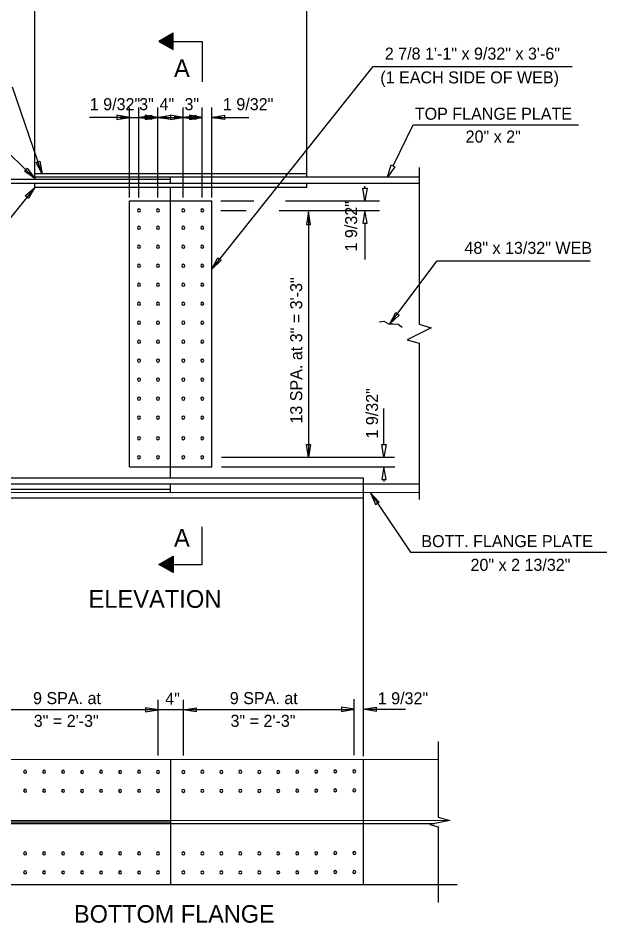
# Model space of a CAD drawing. Extents: x 4944 to 17449, y 3824 to 49087.
# Drawn here: x 13343 to 13907, y 39783 to 40650 of the extents above; entities that cross this region are included whole.
import ezdxf

# ---------------------------------------------------------------- set-up
doc = ezdxf.new("R2010")
doc.units = 0
for name, color, linetype in [('1', 7, 'Continuous'), ('2', 7, 'Continuous'), ('36_S_LINES', 7, 'Continuous'), ('3A', 7, 'Continuous'), ('4', 7, 'Continuous'), ('7', 7, 'Continuous'), ('BEAM', 7, 'Continuous'), ('Level 25', 7, 'Continuous')]:
    doc.layers.add(name, color=color, linetype=linetype)

# ---------------------------------------------------------------- blocks, each defined once
blk = doc.blocks.new('SC1136')
at = {"layer": '1'}
for p, q in [((0.4684, 0.5391), (0.5316, 0.5391)), ((0.4707, 0.543), (0.5293, 0.543)), ((0.4729, 0.5469), (0.5271, 0.5469)), ((0.4752, 0.5508), (0.5248, 0.5508)), ((0.4774, 0.5547), (0.5226, 0.5547)), ((0.4797, 0.5586), (0.5203, 0.5586)), ((0.482, 0.5625), (0.518, 0.5625)), ((0.4842, 0.5664), (0.5158, 0.5664)), ((0.4865, 0.5703), (0.5135, 0.5703)), ((0.4887, 0.5742), (0.5113, 0.5742)), ((0.491, 0.5781), (0.509, 0.5781)), ((0.4932, 0.582), (0.5068, 0.582)), ((0.4955, 0.5859), (0.5045, 0.5859)), ((0.4977, 0.5898), (0.5023, 0.5898)), ((0.4188, 0.4531), (0.5812, 0.4531)), ((0.4211, 0.457), (0.5789, 0.457)), ((0.4233, 0.4609), (0.5767, 0.4609)), ((0.4256, 0.4648), (0.5744, 0.4648)), ((0.4278, 0.4688), (0.5722, 0.4688)), ((0.4301, 0.4727), (0.5699, 0.4727)), ((0.4323, 0.4766), (0.5677, 0.4766)), ((0.4346, 0.4805), (0.5654, 0.4805)), ((0.4369, 0.4844), (0.5631, 0.4844)), ((0.4391, 0.4883), (0.5609, 0.4883)), ((0.4414, 0.4922), (0.5586, 0.4922)), ((0.4436, 0.4961), (0.5564, 0.4961)), ((0.4459, 0.5), (0.5541, 0.5)), ((0.4481, 0.5039), (0.5519, 0.5039)), ((0.4504, 0.5078), (0.5496, 0.5078)), ((0.4526, 0.5117), (0.5474, 0.5117)), ((0.4549, 0.5156), (0.5451, 0.5156)), ((0.4571, 0.5195), (0.5429, 0.5195)), ((0.4594, 0.5234), (0.5406, 0.5234)), ((0.4617, 0.5273), (0.5383, 0.5273)), ((0.4639, 0.5312), (0.5361, 0.5312)), ((0.4662, 0.5352), (0.5338, 0.5352))]:
    blk.add_line(p, q, dxfattribs=at)
blk = doc.blocks.new('DWG070')
at = {"layer": '1'}
blk.add_lwpolyline([(0, 0), (0.1406, -0.0812), (0.1406, 0.0812)], close=True, dxfattribs=at)
at = {"layer": '1', "rotation": 90}
blk.add_blockref('SC1136', (0.5945, -0.5), dxfattribs=at)
blk = doc.blocks.new('ARROWH')
at = {"layer": '1'}
blk.add_lwpolyline([(0.1231, -0.0212), (0.1231, 0.0205), (-0.0019, -0.0003)], close=True, dxfattribs=at)

msp = doc.modelspace()

# ---------------------------------------------------------------- linework, layer by layer
at = {"layer": '1'}
for centre, start, end in [((13458.76, 40465.41), 0, 180), ((13476.95, 40465.41), 0, 180), ((13501.21, 40465.41), 0, 180), ((13519.4, 40465.41), 0, 180), ((13458.76, 40465.41), 180, 0), ((13476.95, 40465.41), 180, 0), ((13501.21, 40465.41), 180, 0), ((13519.4, 40465.41), 180, 0), ((13458.76, 40448.76), 0, 180), ((13458.76, 40448.76), 180, 0), ((13476.95, 40448.76), 0, 180), ((13476.95, 40448.76), 180, 0), ((13501.21, 40448.76), 0, 180), ((13501.21, 40448.76), 180, 0), ((13519.4, 40448.76), 0, 180), ((13519.4, 40448.76), 180, 0), ((13458.76, 40430.56), 0, 180), ((13476.95, 40430.56), 0, 180), ((13501.21, 40430.56), 0, 180), ((13519.4, 40430.56), 0, 180), ((13458.76, 40430.56), 180, 0), ((13476.95, 40430.56), 180, 0), ((13501.21, 40430.56), 180, 0), ((13519.4, 40430.56), 180, 0), ((13458.76, 40412.37), 0, 180), ((13476.95, 40412.37), 0, 180), ((13501.21, 40412.37), 0, 180), ((13519.4, 40412.37), 0, 180), ((13458.76, 40412.37), 180, 0), ((13476.95, 40412.37), 180, 0), ((13501.21, 40412.37), 180, 0), ((13519.4, 40412.37), 180, 0), ((13458.76, 40394.18), 0, 180), ((13458.76, 40394.18), 180, 0), ((13476.95, 40394.18), 0, 180), ((13476.95, 40394.18), 180, 0), ((13501.21, 40394.18), 0, 180), ((13501.21, 40394.18), 180, 0), ((13519.4, 40394.18), 0, 180), ((13519.4, 40394.18), 180, 0), ((13458.76, 40375.98), 0, 180), ((13458.76, 40375.98), 180, 0), ((13476.95, 40375.98), 0, 180), ((13476.95, 40375.98), 180, 0), ((13501.21, 40375.98), 0, 180), ((13501.21, 40375.98), 180, 0), ((13519.4, 40375.98), 0, 180), ((13519.4, 40375.98), 180, 0), ((13458.76, 40357.79), 0, 180), ((13458.76, 40357.79), 180, 0), ((13476.95, 40357.79), 0, 180), ((13476.95, 40357.79), 180, 0), ((13501.21, 40357.79), 0, 180), ((13501.21, 40357.79), 180, 0), ((13519.4, 40357.79), 0, 180), ((13519.4, 40357.79), 180, 0), ((13458.76, 40339.6), 0, 180), ((13458.76, 40339.6), 180, 0), ((13476.95, 40339.6), 0, 180), ((13476.95, 40339.6), 180, 0), ((13501.21, 40339.6), 0, 180), ((13501.21, 40339.6), 180, 0), ((13519.4, 40339.6), 0, 180), ((13519.4, 40339.6), 180, 0), ((13458.76, 40321.41), 0, 180), ((13458.76, 40321.41), 180, 0), ((13476.95, 40321.41), 0, 180), ((13476.95, 40321.41), 180, 0), ((13501.21, 40321.41), 0, 180), ((13501.21, 40321.41), 180, 0), ((13519.4, 40321.41), 0, 180), ((13519.4, 40321.41), 180, 0), ((13458.76, 40303.21), 0, 180), ((13458.76, 40303.21), 180, 0), ((13476.95, 40303.21), 0, 180), ((13476.95, 40303.21), 180, 0), ((13501.21, 40303.21), 0, 180), ((13501.21, 40303.21), 180, 0), ((13519.4, 40303.21), 0, 180), ((13519.4, 40303.21), 180, 0), ((13458.76, 40285.02), 0, 180), ((13458.76, 40285.02), 180, 0), ((13476.95, 40285.02), 0, 180), ((13476.95, 40285.02), 180, 0), ((13501.21, 40285.02), 0, 180), ((13501.21, 40285.02), 180, 0), ((13519.4, 40285.02), 0, 180), ((13519.4, 40285.02), 180, 0), ((13458.76, 40266.83), 0, 180), ((13458.76, 40266.83), 180, 0), ((13476.95, 40266.83), 0, 180), ((13476.95, 40266.83), 180, 0), ((13501.21, 40266.83), 0, 180), ((13501.21, 40266.83), 180, 0), ((13519.4, 40266.83), 0, 180), ((13519.4, 40266.83), 180, 0), ((13458.76, 40247.09), 0, 180), ((13458.76, 40247.09), 180, 0), ((13476.95, 40247.09), 0, 180), ((13476.95, 40247.09), 180, 0), ((13501.21, 40247.09), 0, 180), ((13501.21, 40247.09), 180, 0), ((13519.4, 40247.09), 0, 180), ((13519.4, 40247.09), 180, 0), ((13458.76, 40228.9), 0, 180), ((13458.76, 40228.9), 180, 0), ((13476.95, 40228.9), 0, 180), ((13476.95, 40228.9), 180, 0), ((13501.21, 40228.9), 0, 180), ((13501.21, 40228.9), 180, 0), ((13519.4, 40228.9), 0, 180), ((13519.4, 40228.9), 180, 0), ((13349.66, 39927.54), 0, 180), ((13367.86, 39927.48), 0, 180), ((13386.05, 39927.42), 0, 180), ((13404.24, 39927.37), 0, 180), ((13422.43, 39927.42), 0, 180), ((13440.63, 39927.37), 0, 180), ((13458.82, 39927.42), 0, 180), ((13477.01, 39927.37), 0, 180), ((13501.27, 39927.37), 0, 180), ((13519.46, 39927.42), 0, 180), ((13537.66, 39927.37), 0, 180), ((13555.85, 39927.42), 0, 180), ((13574.04, 39927.37), 0, 180), ((13592.23, 39927.31), 0, 180), ((13610.43, 39927.48), 0, 180), ((13628.62, 39927.65), 0, 180), ((13646.81, 39927.82), 0, 180), ((13665, 39927.88), 0, 180), ((13349.66, 39927.54), 180, 0), ((13367.86, 39927.48), 180, 0), ((13386.05, 39927.42), 180, 0), ((13404.24, 39927.37), 180, 0), ((13422.43, 39927.42), 180, 0), ((13440.63, 39927.37), 180, 0), ((13458.82, 39927.42), 180, 0), ((13477.01, 39927.37), 180, 0), ((13501.27, 39927.37), 180, 0), ((13519.46, 39927.42), 180, 0), ((13537.66, 39927.37), 180, 0), ((13555.85, 39927.42), 180, 0), ((13574.04, 39927.37), 180, 0), ((13592.23, 39927.31), 180, 0), ((13610.43, 39927.48), 180, 0), ((13628.62, 39927.65), 180, 0), ((13646.81, 39927.82), 180, 0), ((13665, 39927.88), 180, 0), ((13628.62, 39909.4), 0, 180), ((13646.81, 39909.57), 0, 180), ((13665, 39909.63), 0, 180), ((13349.66, 39909.29), 0, 180), ((13349.66, 39909.29), 180, 0), ((13367.86, 39909.23), 0, 180), ((13367.86, 39909.23), 180, 0), ((13386.05, 39909.17), 0, 180), ((13386.05, 39909.17), 180, 0), ((13404.24, 39909.12), 0, 180), ((13404.24, 39909.12), 180, 0), ((13422.43, 39909.17), 0, 180), ((13422.43, 39909.17), 180, 0), ((13440.63, 39909.12), 0, 180), ((13440.63, 39909.12), 180, 0), ((13458.82, 39909.17), 0, 180), ((13458.82, 39909.17), 180, 0), ((13477.01, 39909.12), 0, 180), ((13477.01, 39909.12), 180, 0), ((13501.27, 39909.12), 0, 180), ((13501.27, 39909.12), 180, 0), ((13519.46, 39909.17), 0, 180), ((13519.46, 39909.17), 180, 0), ((13537.66, 39909.12), 0, 180), ((13537.66, 39909.12), 180, 0), ((13555.85, 39909.17), 0, 180), ((13555.85, 39909.17), 180, 0), ((13574.04, 39909.12), 0, 180), ((13574.04, 39909.12), 180, 0), ((13592.23, 39909.06), 0, 180), ((13592.23, 39909.06), 180, 0), ((13610.43, 39909.23), 0, 180), ((13610.43, 39909.23), 180, 0), ((13628.62, 39909.4), 180, 0), ((13646.81, 39909.57), 180, 0), ((13665, 39909.63), 180, 0), ((13349.66, 39849.29), 0, 180), ((13367.86, 39849.23), 0, 180), ((13386.05, 39849.17), 0, 180), ((13404.24, 39849.23), 0, 180), ((13422.43, 39849.17), 0, 180), ((13440.63, 39849.23), 0, 180), ((13458.82, 39849.17), 0, 180), ((13477.01, 39849.23), 0, 180), ((13501.27, 39849.23), 0, 180), ((13519.46, 39849.17), 0, 180), ((13537.66, 39849.23), 0, 180), ((13555.85, 39849.17), 0, 180), ((13574.04, 39849.23), 0, 180), ((13592.23, 39849.17), 0, 180), ((13610.43, 39849.23), 0, 180), ((13628.62, 39849.4), 0, 180), ((13646.81, 39849.57), 0, 180), ((13665, 39849.63), 0, 180), ((13349.66, 39849.29), 180, 0), ((13367.86, 39849.23), 180, 0), ((13386.05, 39849.17), 180, 0), ((13404.24, 39849.23), 180, 0), ((13422.43, 39849.17), 180, 0), ((13440.63, 39849.23), 180, 0), ((13458.82, 39849.17), 180, 0), ((13477.01, 39849.23), 180, 0), ((13501.27, 39849.23), 180, 0), ((13519.46, 39849.17), 180, 0), ((13537.66, 39849.23), 180, 0), ((13555.85, 39849.17), 180, 0), ((13574.04, 39849.23), 180, 0), ((13592.23, 39849.17), 180, 0), ((13610.43, 39849.23), 180, 0), ((13628.62, 39849.4), 180, 0), ((13646.81, 39849.57), 180, 0), ((13665, 39849.63), 180, 0), ((13646.81, 39831.32), 0, 180), ((13665, 39831.38), 0, 180), ((13349.66, 39831.04), 0, 180), ((13349.66, 39831.04), 180, 0), ((13367.86, 39830.98), 0, 180), ((13367.86, 39830.98), 180, 0), ((13386.05, 39830.92), 0, 180), ((13386.05, 39830.92), 180, 0), ((13404.24, 39830.98), 0, 180), ((13404.24, 39830.98), 180, 0), ((13422.43, 39830.92), 0, 180), ((13422.43, 39830.92), 180, 0), ((13440.63, 39830.98), 0, 180), ((13440.63, 39830.98), 180, 0), ((13458.82, 39830.92), 0, 180), ((13458.82, 39830.92), 180, 0), ((13477.01, 39830.98), 0, 180), ((13477.01, 39830.98), 180, 0), ((13501.27, 39830.98), 0, 180), ((13501.27, 39830.98), 180, 0), ((13519.46, 39830.92), 0, 180), ((13519.46, 39830.92), 180, 0), ((13537.66, 39830.98), 0, 180), ((13537.66, 39830.98), 180, 0), ((13555.85, 39830.92), 0, 180), ((13555.85, 39830.92), 180, 0), ((13574.04, 39830.98), 0, 180), ((13574.04, 39830.98), 180, 0), ((13592.23, 39830.92), 0, 180), ((13592.23, 39830.92), 180, 0), ((13610.43, 39830.98), 0, 180), ((13610.43, 39830.98), 180, 0), ((13628.62, 39831.15), 0, 180), ((13628.62, 39831.15), 180, 0), ((13646.81, 39831.32), 180, 0), ((13665, 39831.38), 180, 0)]:
    msp.add_arc(centre, 1.42, start, end, dxfattribs=at)
at = {"layer": '2'}
for p, q in [((13489.08, 40219.8), (13489.08, 40474.5)), ((13489.14, 39819.23), (13489.14, 39939.23))]:
    msp.add_line(p, q, dxfattribs=at)
at = {"layer": '36_S_LINES'}
for p, q in [((13528.5, 40409.15), (13683.19, 40603.17)), ((13683.19, 40603.17), (13873.96, 40603.17)), ((13365.88, 40500.53), (13337.58, 40583.35)), ((13449.67, 40477.76), (13449.67, 40564.15)), ((13528.5, 40477.76), (13528.5, 40564.15)), ((13449.67, 40554.52), (13411.48, 40554.52)), ((13440.57, 40554.52), (13458.76, 40554.52)), ((13458.76, 40554.52), (13501.21, 40554.52)), ((13458.76, 40554.52), (13483.02, 40554.52)), ((13476.95, 40554.52), (13501.21, 40554.52)), ((13476.95, 40554.52), (13519.4, 40554.52)), ((13501.21, 40554.52), (13501.21, 40554.52)), ((13519.4, 40554.52), (13501.21, 40554.52)), ((13528.5, 40554.52), (13564.13, 40554.52)), ((13358.94, 40496.03), (13306.79, 40546.64)), ((13702.23, 40508.05), (13721.38, 40547.4)), ((13721.38, 40547.4), (13879.76, 40547.4)), ((13727.15, 40506.65), (13727.15, 40356.24)), ((13358.94, 40487.4), (13307.06, 40423.34)), ((13675.26, 40486.63), (13675.26, 40488.57)), ((13537.29, 40474.5), (13568.93, 40474.5)), ((13599.22, 40474.5), (13689.29, 40474.5)), ((13621.24, 40463.87), (13621.24, 40230.44)), ((13675.26, 40453.28), (13675.26, 40418.4)), ((13699.09, 40356.67), (13744.56, 40417.05)), ((13744.56, 40417.05), (13891.11, 40417.05)), ((13688.79, 40358.47), (13693.4, 40359.33)), ((13693.4, 40359.33), (13697.96, 40356.55)), ((13697.96, 40356.55), (13702.47, 40356.55)), ((13702.47, 40356.55), (13707.03, 40356.5)), ((13707.03, 40356.5), (13710.87, 40353.38)), ((13727.15, 40356.24), (13738.67, 40352.83)), ((13738.67, 40352.83), (13715.63, 40341.47)), ((13715.63, 40341.47), (13727.15, 40338.07)), ((13727.15, 40338.07), (13727.15, 40188.44)), ((13693.45, 40241.03), (13693.45, 40275.58)), ((13537.83, 40219.8), (13703.81, 40219.8)), ((13693.45, 40207.68), (13693.45, 40205.65)), ((13680.51, 40194.9), (13718.83, 40137.97)), ((13718.83, 40137.97), (13907.12, 40137.97)), ((13674.04, 39942.4), (13674.04, 39996.92)), ((13313.33, 39987.07), (13664.95, 39987.07)), ((13674.04, 39987.3), (13714.03, 39987.3)), ((13745.4, 39956.37), (13745.4, 39884)), ((13756.77, 39880.82), (13737.37, 39877.04)), ((13737.37, 39877.04), (13745.4, 39874.79)), ((13745.4, 39884), (13756.77, 39880.82)), ((13745.4, 39874.79), (13745.4, 39802.09))]:
    msp.add_line(p, q, dxfattribs=at)
for points in [[(13437.54, 40556.54), (13437.54, 40552.5), (13449.67, 40554.52)], [(13441.69, 40553.51), (13441.69, 40555.53), (13449.67, 40554.52)], [(13470.89, 40556.54), (13470.89, 40552.5), (13458.76, 40554.52)], [(13466.74, 40553.51), (13466.74, 40555.53), (13458.76, 40554.52)], [(13466.76, 40553.51), (13466.76, 40555.53), (13458.76, 40554.52)], [(13466.76, 40555.53), (13466.76, 40553.51), (13458.76, 40554.52)], [(13464.83, 40556.54), (13464.83, 40552.5), (13476.95, 40554.52)], [(13468.96, 40553.51), (13468.96, 40555.53), (13476.95, 40554.52)], [(13468.96, 40555.53), (13468.96, 40553.51), (13476.95, 40554.52)], [(13468.98, 40553.51), (13468.98, 40555.53), (13476.95, 40554.52)], [(13489.08, 40556.54), (13489.08, 40552.5), (13476.95, 40554.52)], [(13484.93, 40553.51), (13484.93, 40555.53), (13476.95, 40554.52)], [(13484.95, 40553.51), (13484.95, 40555.53), (13476.95, 40554.52)], [(13484.95, 40555.53), (13484.95, 40553.51), (13476.95, 40554.52)], [(13489.08, 40556.54), (13489.08, 40552.5), (13501.21, 40554.52)], [(13493.21, 40553.51), (13493.21, 40555.53), (13501.21, 40554.52)], [(13493.21, 40555.53), (13493.21, 40553.51), (13501.21, 40554.52)], [(13493.23, 40553.51), (13493.23, 40555.53), (13501.21, 40554.52)], [(13513.34, 40556.54), (13513.34, 40552.5), (13501.21, 40554.52)], [(13509.19, 40553.51), (13509.19, 40555.53), (13501.21, 40554.52)], [(13509.21, 40553.51), (13509.21, 40555.53), (13501.21, 40554.52)], [(13509.21, 40555.53), (13509.21, 40553.51), (13501.21, 40554.52)], [(13507.28, 40556.54), (13507.28, 40552.5), (13519.4, 40554.52)], [(13511.41, 40553.51), (13511.41, 40555.53), (13519.4, 40554.52)], [(13511.41, 40555.53), (13511.41, 40553.51), (13519.4, 40554.52)], [(13511.42, 40553.51), (13511.42, 40555.53), (13519.4, 40554.52)], [(13540.63, 40556.54), (13540.63, 40552.5), (13528.5, 40554.52)], [(13536.48, 40553.51), (13536.48, 40555.53), (13528.5, 40554.52)], [(13536.5, 40553.51), (13536.5, 40555.53), (13528.5, 40554.52)], [(13536.5, 40555.53), (13536.5, 40553.51), (13528.5, 40554.52)], [(13363.9, 40512.53), (13365.88, 40500.53), (13360.11, 40511.24)], [(13351.72, 40505.82), (13358.94, 40496.03), (13348.93, 40502.95)], [(13700.42, 40508.93), (13704.05, 40507.17), (13696.93, 40497.14)], [(13349.83, 40479.34), (13358.94, 40487.4), (13352.94, 40476.82)], [(13673.24, 40486.63), (13677.28, 40486.63), (13675.26, 40474.5)], [(13619.22, 40451.74), (13623.26, 40451.74), (13621.24, 40463.87)], [(13673.24, 40453.28), (13677.28, 40453.28), (13675.26, 40465.41)], [(13534.25, 40420.01), (13537.47, 40417.56), (13528.5, 40409.15)], [(13704.84, 40367.54), (13708.06, 40365.08), (13699.09, 40356.67)], [(13619.22, 40241.03), (13623.26, 40241.03), (13621.24, 40228.9)], [(13691.43, 40241.03), (13695.47, 40241.03), (13693.45, 40228.9)], [(13691.43, 40207.68), (13695.47, 40207.68), (13693.45, 40219.8)], [(13464.88, 39988.86), (13464.88, 39984.82), (13477.01, 39986.84)], [(13513.4, 39988.86), (13513.4, 39984.82), (13501.27, 39986.84)], [(13652.82, 39989.32), (13652.82, 39985.28), (13664.95, 39987.3)], [(13686.17, 39989.32), (13686.17, 39985.28), (13674.04, 39987.3)]]:
    msp.add_lwpolyline(points, close=True, dxfattribs=at)
at = {"layer": '3A'}
for p, q in [((13458.76, 40477.76), (13458.76, 40564.15)), ((13476.95, 40477.76), (13476.95, 40564.15)), ((13501.21, 40477.76), (13501.21, 40564.15)), ((13519.4, 40477.76), (13519.4, 40564.15)), ((13537.29, 40465.41), (13561.38, 40465.41)), ((13592.96, 40465.41), (13689.29, 40465.41)), ((13537.83, 40228.9), (13703.5, 40228.9)), ((13477.01, 39943.01), (13477.01, 39996.46)), ((13501.27, 39943.01), (13501.27, 39996.46)), ((13664.95, 39943.47), (13664.95, 39996.92))]:
    msp.add_line(p, q, dxfattribs=at)
at = {"layer": '4'}
for p, q in [((13477.8, 40627.12), (13519.24, 40627.12)), ((13519.24, 40627.12), (13519.24, 40588.53)), ((13519.24, 40126.19), (13519.24, 40162.31)), ((13477.8, 40126.19), (13519.24, 40126.19))]:
    msp.add_line(p, q, dxfattribs=at)
at = {"layer": '7'}
for p, q in [((13222.06, 39880.86), (13756.23, 39880.97)), ((13236.28, 39877.83), (13742, 39877.94))]:
    msp.add_line(p, q, dxfattribs=at)
at = {"layer": 'DEFPOINTS'}
for p, q in [((13358.58, 40810.85), (13358.58, 40500.53)), ((13619.23, 40810.85), (13619.23, 40500.53)), ((13674.04, 39987.3), (13674.04, 40208.78)), ((13489.14, 39879.28), (12935.36, 39879.28))]:
    msp.add_line(p, q, dxfattribs=at)
at = {"layer": 'Level 25'}
for p, q in [((13619.59, 40500.53), (13358.94, 40500.53)), ((13358.94, 40497.15), (13358.94, 40500.53)), ((13619.59, 40497.15), (13619.59, 40500.53)), ((13489.08, 40494.9), (13251.02, 40494.9)), ((13727.15, 40497.15), (13358.94, 40497.15)), ((13358.94, 40497.15), (13358.94, 40494.9)), ((13489.08, 40491.15), (13489.08, 40497.15)), ((13727.15, 40491.15), (13251.02, 40491.15)), ((13358.94, 40487.4), (13358.94, 40491.15)), ((13619.59, 40487.4), (13358.94, 40487.4)), ((13489.08, 40474.5), (13489.08, 40487.4)), ((13619.59, 40487.4), (13619.59, 40491.15)), ((13449.67, 40474.5), (13528.5, 40474.5)), ((13449.67, 40219.8), (13449.67, 40474.5)), ((13528.5, 40219.8), (13528.5, 40474.5)), ((13449.67, 40219.8), (13528.5, 40219.8)), ((13489.08, 40208.72), (13489.08, 40219.8)), ((13673.93, 40208.78), (13304.12, 40208.78)), ((13673.93, 40203.21), (13673.93, 40208.78)), ((13727.15, 40203.15), (13250.65, 40203.15)), ((13489.08, 40197.9), (13251.02, 40197.9)), ((13489.08, 40194.9), (13489.08, 40203.15)), ((13727.15, 40194.9), (13304.12, 40194.97)), ((13673.93, 40189.67), (13304.12, 40189.72)), ((13673.93, 40189.67), (13673.93, 40194.96)), ((13232.88, 39939.28), (13745.4, 39939.4)), ((13674.04, 39819.68), (13674.04, 39939.57)), ((13232.88, 39819.45), (13763.59, 39819.57))]:
    msp.add_line(p, q, dxfattribs=at)

# ---------------------------------------------------------------- block references
at = {"layer": '36_S_LINES', "xscale": 97.02800408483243, "yscale": 97.02800408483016, "rotation": -56.61183182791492}
msp.add_blockref('ARROWH', (13680.63, 40194.77), dxfattribs=at)
at = {"layer": '4', "xscale": 97.02800408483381}
for p, yscale in [((13477.8, 40627.34), 97.02800408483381), ((13477.8, 40126.19), -97.02800408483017)]:
    msp.add_blockref('DWG070', p, dxfattribs=dict(at, yscale=yscale))

# ---------------------------------------------------------------- texts
at = {"layer": '3A'}
for s, p in [('2 7/8 1\'-1" x 9/32" x 3\'-6"', (13694.29, 40609.89)), ('(1 EACH SIDE OF WEB)', (13690.01, 40587.1)), ('1 9/32"', (13411.61, 40561.44)), ('3"', (13458.92, 40561.44)), ('4"', (13478.45, 40561.44)), ('3"', (13502.34, 40561.44)), ('1 9/32"', (13539.2, 40561.44)), ('TOP FLANGE PLATE', (13723.06, 40552.26)), ('20" x 2"', (13771.75, 40530.44)), ('48" x 13/32" WEB', (13770.63, 40423.76)), ('BOTT. FLANGE PLATE', (13729.31, 40142.71)), ('20" x 2 13/32"', (13776.44, 40120)), ('9 SPA. at', (13357.23, 39992.27)), ('4"', (13483.91, 39991.65)), ('9 SPA. at', (13545.78, 39992.27)), ('1 9/32"', (13687.56, 39992.1)), ('3" = 2\'-3"', (13357.9, 39970.49)), ('3" = 2\'-3"', (13546.45, 39970.49))]:
    msp.add_text(s, height=11.52, dxfattribs=at).set_placement(p)
for s, p in [('1 9/32"', (13667.76, 40426.01)), ('13 SPA. at 3" = 3\'-3"', (13615.16, 40261.08)), ('1 9/32"', (13687.8, 40246.76))]:
    msp.add_text(s, height=11.52, rotation=90, dxfattribs=at).set_placement(p)
at = {"layer": 'BEAM'}
for s, height, p in [('A', 16.98, (13492.3, 40593.2)), ('A', 16.98, (13492.3, 40143.13)), ('ELEVATION', 16.98, (13410.31, 40084.56)), ('BOTTOM FLANGE', 16.8, (13396.52, 39782.86))]:
    msp.add_text(s, height=height, dxfattribs=at).set_placement(p)

doc.saveas('drawing.dxf')
